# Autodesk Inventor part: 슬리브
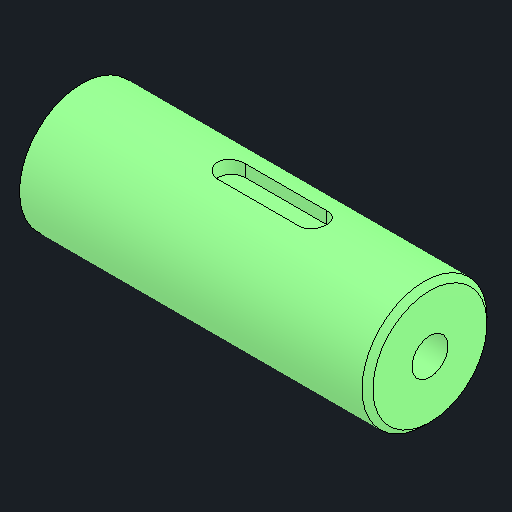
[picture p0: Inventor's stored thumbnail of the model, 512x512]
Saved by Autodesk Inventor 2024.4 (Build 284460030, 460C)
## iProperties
Created: 2026-08
Part Number: 슬리브
Material: 강철, 탄소
Document SubType Name: Modeling
Designer: user
Density: 7.87 g/cm^3
Appearance: 기본값
Author: jhkim
Sending System: Autodesk Inventor 2027
Preprocessor: ST-DEVELOPER v20.1
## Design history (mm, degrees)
feature "솔리드1"
node "솔리드2"
